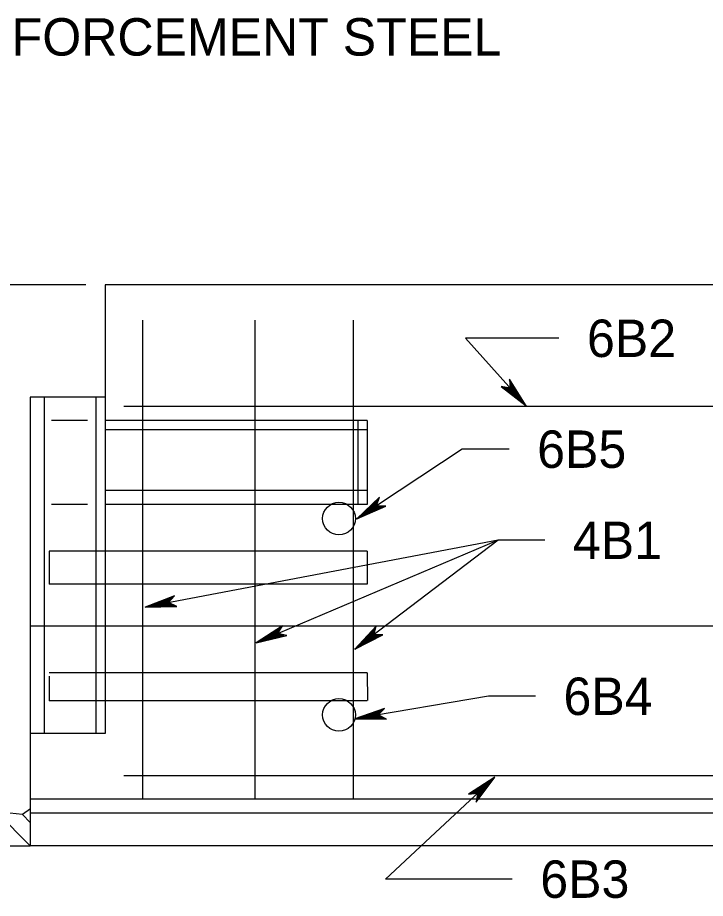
# Model space of a CAD drawing. Extents: x 499866 to 500993, y 499985 to 500645.
# Drawn here: x 500165.5 to 500238.9, y 500456.9 to 500551.1 of the extents above; entities that cross this region are included whole.
import ezdxf

# ---------------------------------------------------------------- set-up
doc = ezdxf.new("R2010")
doc.units = 0
for name, color, linetype in [('24', 7, 'Continuous'), ('5', 7, 'Continuous'), ('60', 7, 'Continuous')]:
    doc.layers.add(name, color=color, linetype=linetype)

msp = doc.modelspace()

# ---------------------------------------------------------------- linework, layer by layer
at = {"layer": '24'}
msp.add_lwpolyline([(500216.441, 500469.907), (500213.61, 500468.069), (500214.592, 500468.181), (500214.418, 500467.228), (500216.441, 500469.907), (500216.284, 500469.752), (500213.708, 500468.101), (500214.642, 500468.218), (500214.485, 500467.353), (500216.204, 500469.663), (500216.112, 500469.6), (500213.914, 500468.176), (500214.654, 500468.23), (500214.527, 500467.495), (500216.074, 500469.566), (500216.005, 500469.478), (500214.08, 500468.238), (500214.667, 500468.251), (500214.616, 500467.65), (500215.771, 500469.259), (500215.634, 500469.131), (500214.259, 500468.29), (500214.686, 500468.283), (500214.67, 500467.816), (500215.598, 500469.12), (500215.461, 500469.007), (500214.454, 500468.345), (500214.779, 500468.333), (500214.753, 500467.998), (500215.348, 500468.888), (500215.215, 500468.786), (500214.601, 500468.399), (500214.796, 500468.362), (500214.775, 500468.1), (500215.163, 500468.715), (500214.748, 500468.478), (500214.884, 500468.431), (500214.821, 500468.199), (500215.089, 500468.622), (500214.814, 500468.47), (500214.976, 500468.484), (500214.909, 500468.34), (500214.952, 500468.508), (500214.885, 500468.468)], dxfattribs=at)
at = {"layer": '5'}
for p, q in [((500172.724, 500522.518), (500151.488, 500522.518)), ((500248.021, 500522.518), (500174.797, 500522.518)), ((500174.797, 500522.518), (500174.797, 500510.527)), ((500178.794, 500518.73), (500178.794, 500467.56)), ((500190.785, 500518.73), (500190.785, 500467.56)), ((500201.277, 500518.73), (500201.277, 500467.56)), ((500223.27, 500516.805), (500213.278, 500516.805)), ((500213.278, 500516.805), (500219.755, 500509.574)), ((500166.803, 500510.527), (500166.803, 500462.564)), ((500174.797, 500510.527), (500166.803, 500510.527)), ((500168.302, 500510.527), (500168.302, 500474.554)), ((500173.798, 500510.527), (500173.798, 500474.554)), ((500174.797, 500510.527), (500174.797, 500474.554)), ((500248.021, 500509.528), (500176.796, 500509.528)), ((500172.908, 500508.029), (500169.064, 500508.029)), ((500202.776, 500508.029), (500174.797, 500508.029)), ((500201.777, 500508.029), (500201.777, 500499.036)), ((500202.776, 500508.029), (500202.776, 500499.036)), ((500202.776, 500507.03), (500174.797, 500507.03)), ((500212.951, 500504.955), (500201.679, 500497.524)), ((500217.948, 500504.955), (500212.951, 500504.955)), ((500202.776, 500500.535), (500174.797, 500500.535)), ((500172.908, 500499.036), (500169.064, 500499.036)), ((500202.776, 500499.036), (500174.797, 500499.036)), ((500216.767, 500495.214), (500179.084, 500488.084)), ((500216.767, 500495.214), (500190.934, 500484.268)), ((500216.767, 500495.214), (500201.478, 500483.565)), ((500221.763, 500495.214), (500216.767, 500495.214)), ((500202.776, 500494.039), (500168.802, 500494.039)), ((500168.802, 500494.039), (500168.802, 500490.542)), ((500202.776, 500494.039), (500202.776, 500490.542)), ((500202.776, 500490.542), (500168.802, 500490.542)), ((500248.021, 500486.046), (500166.803, 500486.046)), ((500202.776, 500481.05), (500168.802, 500481.05)), ((500168.806, 500480.677), (500168.835, 500478.052)), ((500202.776, 500481.05), (500202.808, 500478.098)), ((500215.763, 500478.544), (500201.478, 500476.134)), ((500220.76, 500478.544), (500215.763, 500478.544)), ((500202.776, 500478.052), (500168.835, 500478.052)), ((500174.797, 500474.554), (500166.803, 500474.554)), ((500248.021, 500470.058), (500176.796, 500470.058)), ((500204.751, 500458.999), (500216.441, 500469.907)), ((500248.021, 500467.56), (500166.803, 500467.56)), ((500166.803, 500467.56), (500166.803, 500467.56)), ((500162.99, 500466.378), (500166.803, 500462.564)), ((500165.966, 500465.899), (500166.803, 500465.062)), ((500248.021, 500466.061), (500166.803, 500466.061)), ((500248.021, 500462.564), (500166.803, 500462.564)), ((500218.282, 500458.999), (500204.751, 500458.999))]:
    msp.add_line(p, q, dxfattribs=at)
for points in [[(500219.755, 500509.574), (500217.975, 500512.442), (500218.067, 500511.459), (500217.118, 500511.652), (500219.755, 500509.574), (500219.603, 500509.735), (500218.005, 500512.344), (500218.103, 500511.408), (500217.241, 500511.582), (500219.516, 500509.817), (500219.454, 500509.91), (500218.075, 500512.137), (500218.115, 500511.395), (500217.382, 500511.537), (500219.421, 500509.948), (500219.335, 500510.019), (500218.134, 500511.969), (500218.136, 500511.383), (500217.535, 500511.446), (500219.12, 500510.258), (500218.995, 500510.398), (500218.183, 500511.789), (500218.167, 500511.362), (500217.7, 500511.387), (500218.986, 500510.434), (500218.875, 500510.573), (500218.234, 500511.592), (500218.215, 500511.269), (500217.881, 500511.301), (500218.758, 500510.688), (500218.659, 500510.823), (500218.285, 500511.445), (500218.244, 500511.251), (500217.982, 500511.277), (500218.589, 500510.877), (500218.361, 500511.297), (500218.311, 500511.162), (500218.08, 500511.229), (500218.498, 500510.953), (500218.351, 500511.231), (500218.362, 500511.069), (500218.219, 500511.138), (500218.386, 500511.092), (500218.348, 500511.159)], [(500201.679, 500497.524), (500204.777, 500498.863), (500203.791, 500498.916), (500204.121, 500499.826), (500201.679, 500497.524), (500201.86, 500497.651), (500204.676, 500498.848), (500203.735, 500498.888), (500204.034, 500499.715), (500201.954, 500497.724), (500202.055, 500497.772), (500204.46, 500498.808), (500203.721, 500498.879), (500203.969, 500499.582), (500202.097, 500497.799), (500202.18, 500497.874), (500204.286, 500498.775), (500203.706, 500498.86), (500203.856, 500499.444), (500202.448, 500498.051), (500202.605, 500498.154), (500204.1, 500498.753), (500203.68, 500498.832), (500203.775, 500499.29), (500202.642, 500498.159), (500202.796, 500498.248), (500203.899, 500498.732), (500203.581, 500498.798), (500203.662, 500499.124), (500202.927, 500498.346), (500203.076, 500498.425), (500203.745, 500498.703), (500203.559, 500498.772), (500203.624, 500499.027), (500203.139, 500498.486), (500203.588, 500498.65), (500203.462, 500498.719), (500203.562, 500498.938), (500203.227, 500498.565), (500203.524, 500498.669), (500203.362, 500498.682), (500203.451, 500498.813), (500203.381, 500498.655), (500203.454, 500498.683)], [(500179.084, 500488.084), (500182.459, 500488.125), (500181.57, 500488.554), (500182.225, 500489.267), (500179.084, 500488.084), (500179.299, 500488.131), (500182.359, 500488.15), (500181.507, 500488.55), (500182.102, 500489.197), (500179.414, 500488.163), (500179.526, 500488.167), (500182.145, 500488.197), (500181.49, 500488.546), (500181.991, 500489.1), (500179.576, 500488.177), (500179.681, 500488.214), (500181.972, 500488.233), (500181.468, 500488.535), (500181.833, 500489.017), (500179.997, 500488.274), (500180.181, 500488.308), (500181.792, 500488.284), (500181.435, 500488.519), (500181.698, 500488.906), (500180.217, 500488.298), (500180.393, 500488.322), (500181.597, 500488.342), (500181.33, 500488.526), (500181.531, 500488.796), (500180.552, 500488.362), (500180.719, 500488.377), (500181.445, 500488.375), (500181.3, 500488.511), (500181.458, 500488.721), (500180.802, 500488.408), (500181.279, 500488.387), (500181.189, 500488.499), (500181.366, 500488.662), (500180.913, 500488.448), (500181.227, 500488.429), (500181.083, 500488.504), (500181.216, 500488.59), (500181.09, 500488.471), (500181.168, 500488.469)], [(500190.934, 500484.268), (500194.223, 500485.023), (500193.263, 500485.255), (500193.753, 500486.09), (500190.934, 500484.268), (500191.135, 500484.36), (500194.121, 500485.027), (500193.203, 500485.237), (500193.647, 500485.996), (500191.24, 500484.415), (500191.348, 500484.444), (500193.901, 500485.028), (500193.187, 500485.23), (500193.559, 500485.878), (500191.395, 500484.463), (500191.49, 500484.521), (500193.724, 500485.027), (500193.169, 500485.215), (500193.422, 500485.762), (500191.786, 500484.647), (500191.958, 500484.72), (500193.538, 500485.038), (500193.139, 500485.192), (500193.315, 500485.625), (500191.996, 500484.718), (500192.163, 500484.778), (500193.335, 500485.054), (500193.035, 500485.177), (500193.174, 500485.482), (500192.31, 500484.851), (500192.47, 500484.901), (500193.179, 500485.053), (500193.009, 500485.155), (500193.119, 500485.394), (500192.544, 500484.95), (500193.014, 500485.029), (500192.903, 500485.12), (500193.041, 500485.317), (500192.645, 500485.011), (500192.955, 500485.06), (500192.799, 500485.102), (500192.91, 500485.215), (500192.812, 500485.072), (500192.889, 500485.086)], [(500201.478, 500483.565), (500204.478, 500485.112), (500203.49, 500485.098), (500203.758, 500486.029), (500201.478, 500483.565), (500201.65, 500483.704), (500204.378, 500485.09), (500203.437, 500485.066), (500203.678, 500485.911), (500201.739, 500483.784), (500201.836, 500483.838), (500204.165, 500485.036), (500203.423, 500485.055), (500203.623, 500485.775), (500201.877, 500483.868), (500201.954, 500483.948), (500203.994, 500484.991), (500203.409, 500485.035), (500203.519, 500485.629), (500202.21, 500484.143), (500202.359, 500484.257), (500203.81, 500484.956), (500203.386, 500485.007), (500203.448, 500485.47), (500202.396, 500484.264), (500202.543, 500484.364), (500203.61, 500484.921), (500203.289, 500484.966), (500203.348, 500485.297), (500202.667, 500484.47), (500202.81, 500484.558), (500203.46, 500484.882), (500203.269, 500484.938), (500203.316, 500485.198), (500202.869, 500484.624), (500203.305, 500484.818), (500203.175, 500484.879), (500203.26, 500485.103), (500202.952, 500484.709), (500203.241, 500484.833), (500203.078, 500484.836), (500203.158, 500484.972), (500203.099, 500484.809), (500203.17, 500484.842)], [(500201.478, 500476.134), (500204.853, 500476.107), (500203.972, 500476.554), (500204.643, 500477.254), (500201.478, 500476.134), (500201.695, 500476.177), (500204.755, 500476.135), (500203.91, 500476.551), (500204.517, 500477.187), (500201.81, 500476.206), (500201.923, 500476.208), (500204.541, 500476.186), (500203.893, 500476.548), (500204.405, 500477.092), (500201.972, 500476.217), (500202.078, 500476.251), (500204.369, 500476.225), (500203.871, 500476.537), (500204.245, 500477.011), (500202.395, 500476.305), (500202.58, 500476.336), (500204.19, 500476.28), (500203.838, 500476.522), (500204.109, 500476.903), (500202.615, 500476.325), (500202.792, 500476.345), (500203.996, 500476.342), (500203.733, 500476.531), (500203.939, 500476.797), (500202.952, 500476.382), (500203.119, 500476.393), (500203.844, 500476.378), (500203.702, 500476.516), (500203.864, 500476.723), (500203.202, 500476.424), (500203.679, 500476.393), (500203.592, 500476.507), (500203.771, 500476.666), (500203.315, 500476.46), (500203.628, 500476.436), (500203.486, 500476.513), (500203.62, 500476.597), (500203.492, 500476.48), (500203.57, 500476.477)], [(500166.835, 500466.517), (500165.966, 500465.899), (500164.615, 500466.065), (500162.769, 500466.421), (500162.298, 500465.635), (500161.826, 500464.85), (500161.198, 500463.593), (500160.413, 500463.75), (500160.59, 500462.573), (500166.803, 500462.564)]]:
    msp.add_lwpolyline(points, dxfattribs=at)
at = {"layer": '60'}
for centre in [(500199.778, 500497.537), (500199.778, 500476.553)]:
    msp.add_circle(centre, 1.749, dxfattribs=at)

# ---------------------------------------------------------------- texts
at = {"layer": '5'}
for s, p in [('REINFORCEMENT STEEL', (500152.039, 500547.022)), ('6B2', (500226.27, 500514.805)), ('6B5', (500220.948, 500502.955)), ('4B1', (500224.763, 500493.214)), ('6B4', (500223.76, 500476.544)), ('6B3', (500221.282, 500456.999))]:
    msp.add_text(s, height=4, dxfattribs=at).set_placement(p)

doc.saveas('drawing.dxf')
